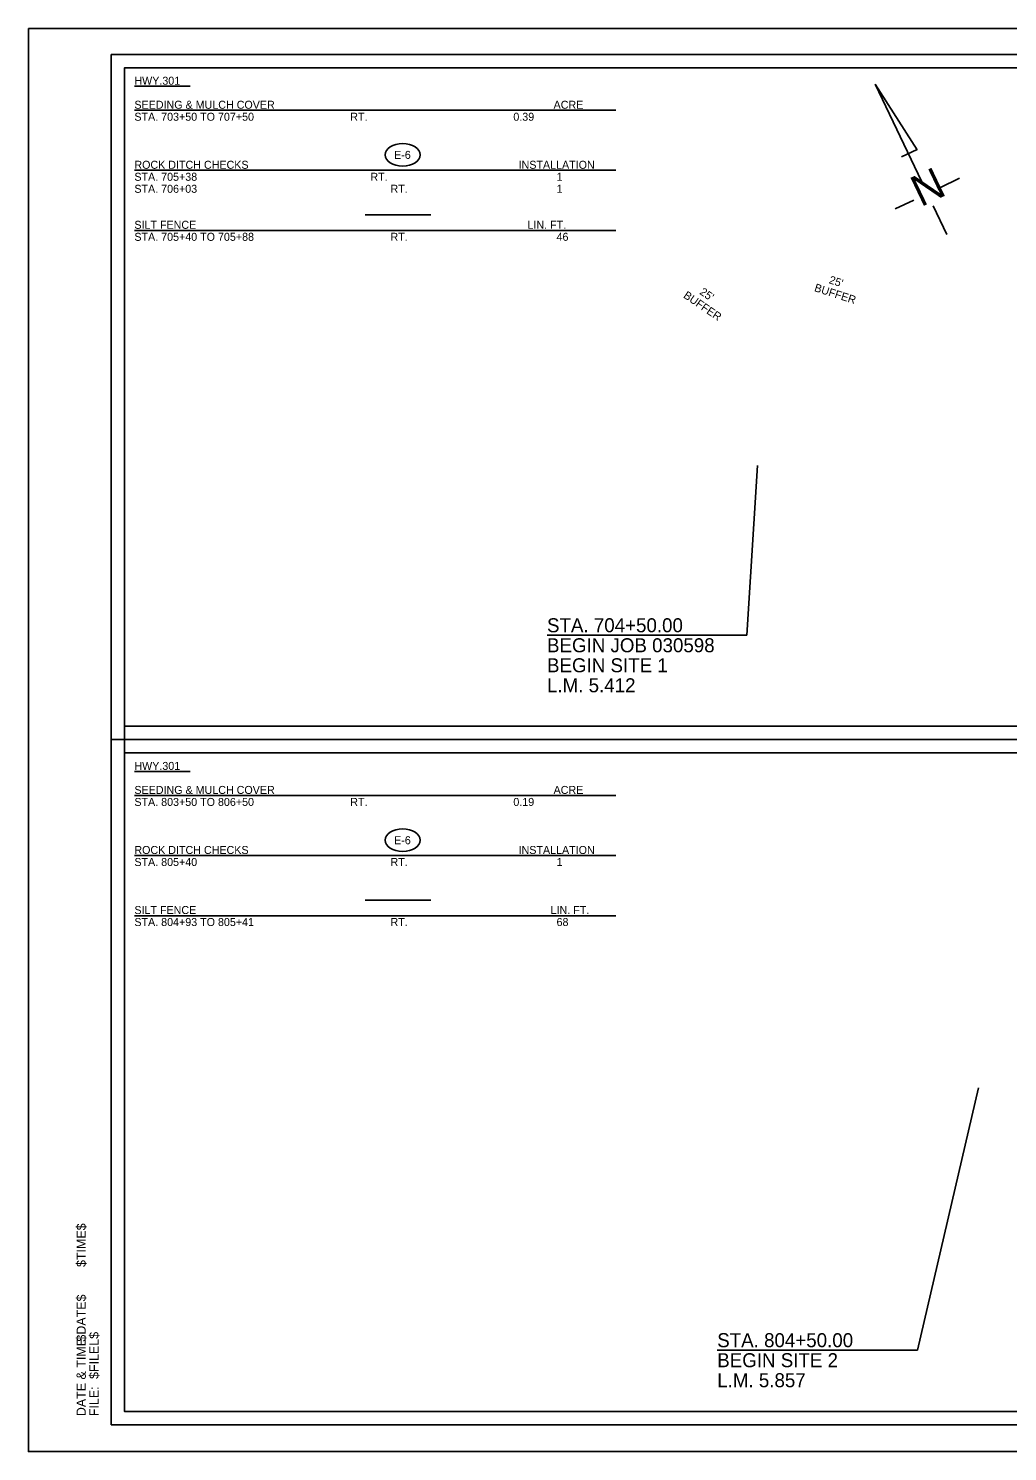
# Model space of a CAD drawing. Extents: x 814841 to 962585, y -174183 to 1802800.
# Drawn here: x 821107 to 821841, y 1801733 to 1802800 of the extents above; entities that cross this region are included whole.
import ezdxf

# ---------------------------------------------------------------- set-up
doc = ezdxf.new("R2010")
doc.units = 0
for name, color, linetype in [('Default', 7, 'Continuous'), ('Erosion Legend', 7, 'Continuous'), ('R_Border', 7, 'Continuous'), ('R_Border Notes', 7, 'Continuous'), ('R_Border Plan-Plan', 7, 'Continuous'), ('R_Detour Annot', 7, 'Continuous'), ('R_Draft', 7, 'Continuous'), ('R_No Plot', 7, 'Continuous'), ('Veg Buffer_Annot', 7, 'Continuous')]:
    doc.layers.add(name, color=color, linetype=linetype)

# ---------------------------------------------------------------- blocks, each defined once
blk = doc.blocks.new('E-6')
at = {"layer": 'Default'}
blk.add_ellipse((0, 0), major_axis=(13.2, 0), ratio=0.638788, dxfattribs=at)
blk.add_text('E-6', height=6, dxfattribs=at).set_placement((-6.4, -3))

msp = doc.modelspace()

# ---------------------------------------------------------------- linework, layer by layer
at = {"layer": 'Erosion Legend'}
for p, q in [((821186.2, 1802756.8), (821227.9, 1802756.8)), ((821186.2, 1802738.8), (821547.2, 1802738.8)), ((821186.2, 1802693.8), (821547.2, 1802693.8)), ((821359.3, 1802660.4), (821408.3, 1802660.4)), ((821186.2, 1802648.6), (821547.2, 1802648.6)), ((821186.2, 1802243.2), (821227.9, 1802243.2)), ((821186.2, 1802225.2), (821547.2, 1802225.2)), ((821186.2, 1802180.2), (821547.2, 1802180.2)), ((821359.3, 1802146.7), (821408.3, 1802146.7)), ((821186.2, 1802134.9), (821547.2, 1802134.9))]:
    msp.add_line(p, q, dxfattribs=at)
at = {"layer": 'R_Border'}
for p, q in [((821168.8, 1802780.6), (822749.7, 1802780.6)), ((821168.8, 1801753.3), (821168.8, 1802780.6)), ((821168.8, 1801753.3), (821168.8, 1801753.3)), ((822749.7, 1801753.3), (821168.8, 1801753.3))]:
    msp.add_line(p, q, dxfattribs=at)
at = {"layer": 'R_Border Plan-Plan'}
msp.add_line((821168.8, 1802267), (822749.7, 1802267), dxfattribs=at)
at = {"layer": 'R_Draft'}
for p, q in [((821741.4, 1802758.4), (821773, 1802709)), ((821776.5, 1802685), (821741.4, 1802758.4)), ((821761.2, 1802703.8), (821772.9, 1802709.4)), ((821789.9, 1802680.7), (821804.7, 1802687.8)), ((821756.4, 1802664.8), (821770.4, 1802671.4)), ((821795.3, 1802645.6), (821785, 1802667.2)), ((821645.3, 1802345.3), (821653.4, 1802472.5)), ((821645.3, 1802345.3), (821495.5, 1802345.3)), ((821773.1, 1801809.3), (821818.9, 1802006.1)), ((821773.1, 1801809.3), (821623.1, 1801809.3))]:
    msp.add_line(p, q, dxfattribs=at)
at = {"layer": 'R_No Plot'}
for points in [[(821106.8, 1802800.1), (822773.5, 1802800.1), (822773.5, 1801733.4), (821106.8, 1801733.4)], [(822739.7, 1802277), (821178.8, 1802277), (821178.8, 1802770.6), (822426.5, 1802770.6), (822426.5, 1802721.2), (822514.2, 1802721.2), (822634.7, 1802721.2), (822634.7, 1802609.5), (822739.7, 1802609.5)], [(822739.7, 1802277), (821178.8, 1802277), (821178.8, 1802770.6), (822426.5, 1802770.6), (822426.5, 1802721.2), (822514.2, 1802721.2), (822634.7, 1802721.2), (822634.7, 1802609.5), (822739.7, 1802609.5)], [(822739.7, 1802277), (821178.8, 1802277), (821178.8, 1802770.6), (822426.5, 1802770.6), (822426.5, 1802721.2), (822514.2, 1802721.2), (822634.7, 1802721.2), (822634.7, 1802609.5), (822739.7, 1802609.5)], [(822739.7, 1802277), (821178.8, 1802277), (821178.8, 1802770.6), (822426.5, 1802770.6), (822426.5, 1802721.2), (822514.2, 1802721.2), (822634.7, 1802721.2), (822634.7, 1802609.5), (822739.7, 1802609.5)], [(822739.7, 1802277), (821178.8, 1802277), (821178.8, 1802770.6), (822426.5, 1802770.6), (822426.5, 1802721.2), (822514.2, 1802721.2), (822634.7, 1802721.2), (822634.7, 1802609.5), (822739.7, 1802609.5)], [(822739.7, 1802277), (821178.8, 1802277), (821178.8, 1802770.6), (822426.5, 1802770.6), (822426.5, 1802721.2), (822514.2, 1802721.2), (822634.7, 1802721.2), (822634.7, 1802609.5), (822739.7, 1802609.5)], [(821178.8, 1802770.6), (822426.5, 1802770.6), (822426.5, 1802721.2), (822514.2, 1802721.2), (822634.7, 1802721.2), (822634.7, 1802609.5), (822739.7, 1802609.5), (822739.7, 1801763.3), (821178.8, 1801763.3)], [(822739.7, 1802277), (821178.8, 1802277), (821178.8, 1802770.6), (822426.5, 1802770.6), (822426.5, 1802721.2), (822514.2, 1802721.2), (822634.7, 1802721.2), (822634.7, 1802609.5), (822739.7, 1802609.5)], [(821178.8, 1802257), (822739.7, 1802257), (822739.7, 1801763.3), (821178.8, 1801763.3)], [(821178.8, 1802257), (822739.7, 1802257), (822739.7, 1801763.3), (821178.8, 1801763.3)], [(821178.8, 1802257), (822739.7, 1802257), (822739.7, 1801763.3), (821178.8, 1801763.3)], [(821178.8, 1802257), (822739.7, 1802257), (822739.7, 1801763.3), (821178.8, 1801763.3)], [(821178.8, 1802257), (822739.7, 1802257), (822739.7, 1801763.3), (821178.8, 1801763.3)], [(821178.8, 1802257), (822739.7, 1802257), (822739.7, 1801763.3), (821178.8, 1801763.3)], [(821178.8, 1802257), (822739.7, 1802257), (822739.7, 1801763.3), (821178.8, 1801763.3)]]:
    msp.add_lwpolyline(points, close=True, dxfattribs=at)

# ---------------------------------------------------------------- block references
at = {"layer": 'Erosion Legend', "rotation": -1.8065126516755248e-10}
for p in [(821387.3, 1802705.3), (821387.3, 1802191.6)]:
    msp.add_blockref('E-6', p, dxfattribs=at)

# ---------------------------------------------------------------- texts
at = {"layer": 'Erosion Legend'}
for s, p in [('HWY.301', (821186.2, 1802757.9)), ('SEEDING & MULCH COVER', (821186.2, 1802739.9)), (' ACRE', (821498.2, 1802739.9)), ('STA. 703+50 TO 707+50', (821186.2, 1802730.9)), ('        RT.    ', (821330.2, 1802730.9)), ('         0.39', (821450.2, 1802730.9)), ('ROCK DITCH CHECKS', (821186.2, 1802694.9)), ('INSTALLATION', (821474.2, 1802694.9)), ('STA. 705+38   ', (821186.2, 1802685.9)), ('STA. 706+03', (821186.2, 1802676.9)), ('    RT.', (821354.2, 1802685.9)), ('RT.', (821378.2, 1802676.9)), ('  1', (821498.2, 1802685.9)), ('  1', (821498.2, 1802676.9)), ('SILT FENCE', (821186.2, 1802649.9)), ('   LIN. FT.', (821474.2, 1802649.9)), ('STA. 705+40 TO 705+88', (821186.2, 1802640.9)), ('RT.', (821378.2, 1802640.9)), ('  46', (821498.2, 1802640.9)), ('HWY.301', (821186.2, 1802244.3)), ('SEEDING & MULCH COVER', (821186.2, 1802226.3)), ('STA. 803+50 TO 806+50', (821186.2, 1802217.3)), ('        RT.    ', (821330.2, 1802217.3)), ('         0.19', (821450.2, 1802217.3)), (' ACRE', (821498.2, 1802226.3)), ('ROCK DITCH CHECKS', (821186.2, 1802181.3)), ('INSTALLATION', (821474.2, 1802181.3)), ('STA. 805+40       ', (821186.2, 1802172.3)), ('RT. ', (821378.2, 1802172.3)), ('  1', (821498.2, 1802172.3)), ('SILT FENCE   ', (821186.2, 1802136.3)), ('LIN. FT.', (821498.2, 1802136.3)), ('STA. 804+93 TO 805+41', (821186.2, 1802127.3)), ('RT. ', (821378.2, 1802127.3)), ('  68', (821498.2, 1802127.3))]:
    msp.add_text(s, height=6, dxfattribs=at).set_placement(p)
at = {"layer": 'R_Border Notes'}
for s, height, p in [('$TIME$', 6.98, (821149.8, 1801871.7)), ('$DATE$', 6.98, (821149.8, 1801815.8)), ('DATE & TIME:', 6.984, (821149.8, 1801759.9)), ('$FILEL$', 6.98, (821159.4, 1801787.8)), ('FILE: ', 6.98, (821159.4, 1801759.9))]:
    msp.add_text(s, height=height, rotation=90, dxfattribs=at).set_placement(p)
at = {"layer": 'R_Detour Annot'}
for s, p in [('STA. 704+50.00', (821495.5, 1802347.5)), ('BEGIN JOB 030598 ', (821495.5, 1802332.5)), ('BEGIN SITE 1', (821495.5, 1802317.5)), ('L.M. 5.412', (821495.5, 1802302.5)), ('STA. 804+50.00 ', (821623.1, 1801811.6)), ('BEGIN SITE 2', (821623.1, 1801796.6)), ('L.M. 5.857', (821623.1, 1801781.6))]:
    msp.add_text(s, height=10.5, dxfattribs=at).set_placement(p)
at = {"layer": 'R_Draft'}
msp.add_text('N', height=23.3, rotation=25.5319, dxfattribs=at).set_placement((821775.7, 1802666))
at = {"layer": 'Veg Buffer_Annot'}
for s, rotation, p in [('BUFFER', 342.1183, (821695.4, 1802603.3)), ("25'", 342.1183, (821706.4, 1802609.2)), ('BUFFER', 325.6564, (821597.2, 1802598.7)), ("25'", 325.6564, (821609.4, 1802601.3))]:
    msp.add_text(s, height=6, rotation=rotation, dxfattribs=at).set_placement(p)

doc.saveas('drawing.dxf')
